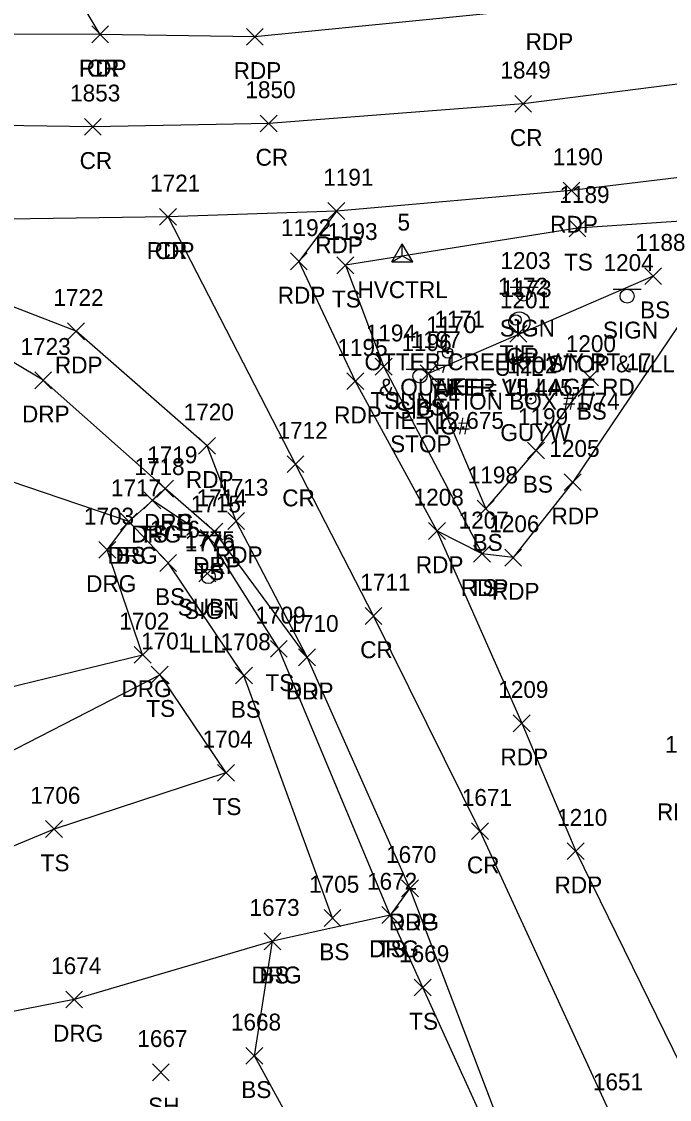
# Model space of a CAD drawing. Extents: x 1443590 to 1445966, y 578314 to 580556.
# Drawn here: x 1445125.4 to 1445202.2, y 578975.6 to 579103.3 of the extents above; entities that cross this region are included whole.
import ezdxf

# ---------------------------------------------------------------- set-up
doc = ezdxf.new("R2010")
doc.units = 0
for name, color, linetype in [('C_A', 7, 'Continuous'), ('C_C', 7, 'Continuous'), ('C_I', 7, 'Continuous'), ('CBP', 7, 'Continuous'), ('CPSM', 7, 'Continuous'), ('L_A', 7, 'Continuous'), ('L_I', 7, 'Continuous'), ('L_TIC', 7, 'Continuous'), ('LELB', 7, 'Continuous'), ('P_A', 7, 'Continuous'), ('P_I', 7, 'Continuous'), ('P_TIC', 7, 'Continuous'), ('PET', 7, 'Continuous'), ('PRC', 7, 'Continuous'), ('R_A', 7, 'Continuous'), ('R_I', 7, 'Continuous'), ('R_TIC', 7, 'Continuous'), ('RDG', 7, 'Continuous'), ('RDP', 7, 'Continuous'), ('RGP', 7, 'Continuous'), ('S_A', 7, 'Continuous'), ('S_C', 7, 'Continuous'), ('S_I', 7, 'Continuous'), ('SSGN', 7, 'Continuous'), ('U_A', 7, 'Continuous'), ('U_C', 7, 'Continuous'), ('U_I', 7, 'Continuous'), ('U_TIC', 7, 'Continuous'), ('UDEFAULT', 7, 'Continuous'), ('UEPT', 7, 'Continuous'), ('UPGW', 7, 'Continuous')]:
    doc.layers.add(name, color=color, linetype=linetype)

msp = doc.modelspace()

# ---------------------------------------------------------------- linework, layer by layer
at = {"layer": 'CBP'}
for centre, radius in [((1445183.97, 579067.97), 0.625), ((1445183.97, 579067.97), 0.0833), ((1445175.88, 579064.07), 0.625), ((1445175.88, 579064.07), 0.0833)]:
    msp.add_circle(centre, radius, dxfattribs=at)
at = {"layer": 'CPSM'}
for p, q in [((1445169.26, 579074.84), (1445170.51, 579077)), ((1445171.76, 579074.84), (1445170.51, 579077)), ((1445170.51, 579075.56), (1445170.51, 579077)), ((1445169.26, 579074.84), (1445170.51, 579075.56)), ((1445170.51, 579075.56), (1445170.51, 579075.56)), ((1445170.51, 579075.56), (1445171.76, 579074.84)), ((1445169.26, 579074.84), (1445171.76, 579074.84))]:
    msp.add_line(p, q, dxfattribs=at)
at = {"layer": 'L_TIC'}
for points in [[(1445190.27, 579077.83), (1445192.27, 579079.83)], [(1445192.27, 579077.83), (1445190.27, 579079.83)], [(1445162.76, 579073.45), (1445164.76, 579075.45)], [(1445164.76, 579073.45), (1445162.76, 579075.45)], [(1445199.25, 579072.16), (1445201.25, 579074.16)], [(1445201.25, 579072.16), (1445199.25, 579074.16)], [(1445167.31, 579061.43), (1445169.31, 579063.43)], [(1445169.31, 579061.43), (1445167.31, 579063.43)], [(1445172.62, 579060.64), (1445174.62, 579062.64)], [(1445174.62, 579060.64), (1445172.62, 579062.64)], [(1445191.75, 579060.16), (1445193.75, 579062.16)], [(1445193.75, 579060.16), (1445191.75, 579062.16)], [(1445185.36, 579051.51), (1445187.36, 579053.51)], [(1445187.36, 579051.51), (1445185.36, 579053.51)], [(1445139.88, 579045.6), (1445141.88, 579047.6)], [(1445141.88, 579045.6), (1445139.88, 579047.6)], [(1445179.4, 579044.61), (1445181.4, 579046.61)], [(1445181.4, 579044.61), (1445179.4, 579046.61)], [(1445137.09, 579043.08), (1445139.09, 579045.08)], [(1445139.09, 579043.08), (1445137.09, 579045.08)], [(1445146.56, 579041.16), (1445148.56, 579043.16)], [(1445148.56, 579041.16), (1445146.56, 579043.16)], [(1445178.96, 579039.26), (1445180.96, 579041.26)], [(1445180.96, 579039.26), (1445178.96, 579041.26)], [(1445141.75, 579038.18), (1445143.75, 579040.18)], [(1445143.75, 579038.18), (1445141.75, 579040.18)], [(1445154.88, 579028), (1445156.88, 579030)], [(1445156.88, 579028), (1445154.88, 579030)], [(1445140.75, 579024.94), (1445142.75, 579026.94)], [(1445142.75, 579024.94), (1445140.75, 579026.94)], [(1445150.74, 579024.84), (1445152.74, 579026.84)], [(1445152.74, 579024.84), (1445150.74, 579026.84)], [(1445148.61, 579013.31), (1445150.61, 579015.31)], [(1445150.61, 579013.31), (1445148.61, 579015.31)], [(1445128.23, 579006.65), (1445130.23, 579008.65)], [(1445130.23, 579006.65), (1445128.23, 579008.65)], [(1445168.07, 578996.46), (1445170.07, 578998.46)], [(1445170.07, 578996.46), (1445168.07, 578998.46)], [(1445161.23, 578996.11), (1445163.23, 578998.11)], [(1445163.23, 578996.11), (1445161.23, 578998.11)], [(1445154.13, 578993.36), (1445156.13, 578995.36)], [(1445156.13, 578993.36), (1445154.13, 578995.36)], [(1445171.93, 578987.88), (1445173.93, 578989.88)], [(1445173.93, 578987.88), (1445171.93, 578989.88)], [(1445151.98, 578979.78), (1445153.98, 578981.78)], [(1445153.98, 578979.78), (1445151.98, 578981.78)], [(1445140.89, 578977.83), (1445142.89, 578979.83)], [(1445142.89, 578977.83), (1445140.89, 578979.83)]]:
    msp.add_lwpolyline(points, dxfattribs=at)
at = {"layer": 'LELB'}
for points in [[(1445162.23, 578997.11), (1445151.74, 579025.84), (1445142.75, 579039.18), (1445138.09, 579044.08), (1445116.07, 579051.55), (1445101.92, 579061.67), (1445096.63, 579066.95), (1445066.06, 579065.72), (1445043.59, 579063.21), (1445031.62, 579065.51), (1445012.31, 579070.54), (1445010.25, 579074.37), (1444988.26, 579078.47), (1444956.32, 579080.59), (1444930.53, 579082.81), (1444916.43, 579086.33), (1444911.23, 579088.69), (1444908.49, 579088.65), (1444906.17, 579094.71), (1444893.92, 579096.75), (1444853.12, 579100.69), (1444811.04, 579100.21)], [(1445213.49, 579080.35), (1445191.27, 579078.83), (1445163.76, 579074.45), (1445168.31, 579062.43), (1445179.96, 579040.26)], [(1445200.25, 579073.16), (1445173.62, 579061.64), (1445180.4, 579045.61), (1445186.36, 579052.51), (1445192.75, 579061.16)], [(1445182.47, 578967.95), (1445172.93, 578988.88), (1445169.07, 578997.46), (1445155.88, 579029), (1445147.56, 579042.16), (1445140.88, 579046.6)], [(1445098.85, 579002.94), (1445095.12, 579014.79), (1445092.53, 579021.51), (1445092.27, 579024.59), (1445114.64, 579017.07), (1445121.81, 579015.68), (1445141.75, 579025.94), (1445149.61, 579014.31), (1445129.23, 579007.65), (1445107.45, 578998.59)], [(1445190.79, 578941.35), (1445175.18, 578951.44), (1445164.42, 578959.92), (1445152.98, 578980.78), (1445155.13, 578994.36)]]:
    msp.add_lwpolyline(points, dxfattribs=at)
at = {"layer": 'P_TIC'}
for points in [[(1445133.69, 579100.81), (1445135.69, 579102.81)], [(1445135.69, 579100.81), (1445133.69, 579102.81)], [(1445133.69, 579100.81), (1445135.69, 579102.81)], [(1445135.69, 579100.81), (1445133.69, 579102.81)], [(1445152.03, 579100.52), (1445154.03, 579102.52)], [(1445154.03, 579100.52), (1445152.03, 579102.52)], [(1445183.84, 579092.58), (1445185.84, 579094.58)], [(1445185.84, 579092.58), (1445183.84, 579094.58)], [(1445132.82, 579089.86), (1445134.82, 579091.86)], [(1445134.82, 579089.86), (1445132.82, 579091.86)], [(1445153.68, 579090.25), (1445155.68, 579092.25)], [(1445155.68, 579090.25), (1445153.68, 579092.25)], [(1445189.56, 579082.31), (1445191.56, 579084.31)], [(1445191.56, 579082.31), (1445189.56, 579084.31)], [(1445161.7, 579079.88), (1445163.7, 579081.88)], [(1445163.7, 579079.88), (1445161.7, 579081.88)], [(1445161.7, 579079.88), (1445163.7, 579081.88)], [(1445163.7, 579079.88), (1445161.7, 579081.88)], [(1445141.74, 579079.19), (1445143.74, 579081.19)], [(1445143.74, 579079.19), (1445141.74, 579081.19)], [(1445141.74, 579079.19), (1445143.74, 579081.19)], [(1445143.74, 579079.19), (1445141.74, 579081.19)], [(1445157.25, 579073.91), (1445159.25, 579075.91)], [(1445159.25, 579073.91), (1445157.25, 579075.91)], [(1445130.84, 579065.63), (1445132.84, 579067.63)], [(1445132.84, 579065.63), (1445130.84, 579067.63)], [(1445163.94, 579059.72), (1445165.94, 579061.72)], [(1445165.94, 579059.72), (1445163.94, 579061.72)], [(1445146.37, 579052.06), (1445148.37, 579054.06)], [(1445148.37, 579052.06), (1445146.37, 579054.06)], [(1445156.85, 579049.89), (1445158.85, 579051.89)], [(1445158.85, 579049.89), (1445156.85, 579051.89)], [(1445189.71, 579047.75), (1445191.71, 579049.75)], [(1445191.71, 579047.75), (1445189.71, 579049.75)], [(1445149.81, 579043.14), (1445151.81, 579045.14)], [(1445151.81, 579043.14), (1445149.81, 579045.14)], [(1445173.62, 579041.97), (1445175.62, 579043.97)], [(1445175.62, 579041.97), (1445173.62, 579043.97)], [(1445173.62, 579041.97), (1445175.62, 579043.97)], [(1445175.62, 579041.97), (1445173.62, 579043.97)], [(1445178.96, 579039.26), (1445180.96, 579041.26)], [(1445180.96, 579039.26), (1445178.96, 579041.26)], [(1445182.65, 579038.82), (1445184.65, 579040.82)], [(1445184.65, 579038.82), (1445182.65, 579040.82)], [(1445166.09, 579031.9), (1445168.09, 579033.9)], [(1445168.09, 579031.9), (1445166.09, 579033.9)], [(1445158.22, 579027.01), (1445160.22, 579029.01)], [(1445160.22, 579027.01), (1445158.22, 579029.01)], [(1445183.66, 579019.19), (1445185.66, 579021.19)], [(1445185.66, 579019.19), (1445183.66, 579021.19)], [(1445178.73, 579006.4), (1445180.73, 579008.4)], [(1445180.73, 579006.4), (1445178.73, 579008.4)], [(1445190.07, 579004.03), (1445192.07, 579006.03)], [(1445192.07, 579004.03), (1445190.07, 579006.03)], [(1445170.41, 578999.64), (1445172.41, 579001.64)], [(1445172.41, 578999.64), (1445170.41, 579001.64)]]:
    msp.add_lwpolyline(points, dxfattribs=at)
at = {"layer": 'PET'}
for points in [[(1445501.67, 579168.43), (1445455.4, 579157.53), (1445415.83, 579148.65), (1445383.99, 579140.98), (1445332.83, 579129.97), (1445290.54, 579120.7), (1445257.45, 579113.85), (1445222.94, 579108.87), (1445187.64, 579104.95), (1445153.03, 579101.52), (1445134.69, 579101.81), (1445094.76, 579101.93)], [(1445505.3, 579147.27), (1445460.87, 579137.08), (1445420.41, 579128.61), (1445387.54, 579120.65), (1445337.52, 579109.35), (1445293.82, 579099.75), (1445262.55, 579093.02), (1445250.68, 579090.5), (1445218.05, 579086.64), (1445190.56, 579083.31), (1445162.7, 579080.88), (1445142.74, 579080.19), (1445099.09, 579079.55)], [(1445218.05, 579086.64), (1445213.49, 579080.35), (1445206.62, 579072.29), (1445190.71, 579048.75), (1445183.65, 579039.82), (1445179.96, 579040.26), (1445174.62, 579042.97)], [(1445162.7, 579080.88), (1445158.25, 579074.91), (1445164.94, 579060.72), (1445174.62, 579042.97), (1445184.66, 579020.19), (1445191.07, 579005.03), (1445204.47, 578977.72)], [(1445183.72, 578968.31), (1445171.41, 579000.64), (1445159.22, 579028.01), (1445150.81, 579044.14), (1445147.37, 579053.06), (1445131.84, 579066.63), (1445104.03, 579077.4), (1445099.09, 579079.55)]]:
    msp.add_lwpolyline(points, dxfattribs=at)
at = {"layer": 'PRC'}
for points in [[(1445134.69, 579101.81), (1445120.96, 579124.75), (1445105.7, 579149.31), (1445088.61, 579176.47), (1445062.61, 579215.94), (1445046.37, 579243.3), (1445028.61, 579272.2), (1445009.91, 579303.07), (1444988.59, 579337.21), (1444961.47, 579379.67), (1444937.03, 579417.04), (1444911.02, 579455.05), (1444885.8, 579491.61), (1444860.37, 579528.28), (1444835.41, 579566.04), (1444809.93, 579606.59), (1444790.8, 579639.57), (1444773.48, 579670.26), (1444758.9, 579698.36)], [(1445503.37, 579157.52), (1445457.64, 579146.91), (1445418.46, 579138.08), (1445385.47, 579130.53), (1445335.24, 579119.44), (1445292.05, 579110.36), (1445260.01, 579104.38), (1445221.4, 579098.24), (1445184.84, 579093.58), (1445154.68, 579091.25), (1445133.82, 579090.86), (1445081.89, 579091.59)], [(1445428.76, 578345.92), (1445416.12, 578381.06), (1445402.82, 578417.2), (1445394.53, 578440.03), (1445382.79, 578472.56), (1445367.55, 578515.78), (1445354.3, 578552.77), (1445340.07, 578591.68), (1445332.93, 578610.75), (1445320.05, 578646.79), (1445306.48, 578683.94), (1445294.78, 578715.83), (1445285.68, 578740.23), (1445278.69, 578759.19), (1445266.72, 578790.29), (1445259.42, 578810.95), (1445240.14, 578861.33), (1445228.56, 578891.21), (1445209.9, 578937.12), (1445195.27, 578973.7), (1445179.73, 579007.4), (1445167.09, 579032.9), (1445157.85, 579050.89), (1445142.74, 579080.19)]]:
    msp.add_lwpolyline(points, dxfattribs=at)
at = {"layer": 'R_TIC'}
for points in [[(1445126.94, 579059.83), (1445128.94, 579061.83)], [(1445128.94, 579059.83), (1445126.94, 579061.83)], [(1445141.4, 579046.99), (1445143.4, 579048.99)], [(1445143.4, 579046.99), (1445141.4, 579048.99)], [(1445141.4, 579046.99), (1445143.4, 579048.99)], [(1445143.4, 579046.99), (1445141.4, 579048.99)], [(1445139.88, 579045.6), (1445141.88, 579047.6)], [(1445141.88, 579045.6), (1445139.88, 579047.6)], [(1445137.09, 579043.08), (1445139.09, 579045.08)], [(1445139.09, 579043.08), (1445137.09, 579045.08)], [(1445147.24, 579041.89), (1445149.24, 579043.89)], [(1445149.24, 579041.89), (1445147.24, 579043.89)], [(1445134.54, 579039.73), (1445136.54, 579041.73)], [(1445136.54, 579039.73), (1445134.54, 579041.73)], [(1445138.73, 579027.29), (1445140.73, 579029.29)], [(1445140.73, 579027.29), (1445138.73, 579029.29)], [(1445158.22, 579027.01), (1445160.22, 579029.01)], [(1445160.22, 579027.01), (1445158.22, 579029.01)], [(1445170.41, 578999.64), (1445172.41, 579001.64)], [(1445172.41, 578999.64), (1445170.41, 579001.64)], [(1445168.07, 578996.46), (1445170.07, 578998.46)], [(1445170.07, 578996.46), (1445168.07, 578998.46)], [(1445154.13, 578993.36), (1445156.13, 578995.36)], [(1445156.13, 578993.36), (1445154.13, 578995.36)], [(1445130.62, 578986.46), (1445132.62, 578988.46)], [(1445132.62, 578986.46), (1445130.62, 578988.46)]]:
    msp.add_lwpolyline(points, dxfattribs=at)
at = {"layer": 'RDG'}
msp.add_lwpolyline([(1445171.41, 579000.64), (1445169.07, 578997.46), (1445155.13, 578994.36), (1445131.62, 578987.46), (1445107.99, 578982.85), (1445100.96, 578995.31), (1445097.63, 579001.55), (1445090.1, 579013.19), (1445087.39, 579022.78), (1445089.24, 579027.02), (1445107.09, 579036.55), (1445117, 579022.75), (1445139.73, 579028.29), (1445135.54, 579040.73), (1445138.09, 579044.08), (1445140.88, 579046.6), (1445142.4, 579047.99)], dxfattribs=at)
at = {"layer": 'RDP'}
msp.add_lwpolyline([(1445159.22, 579028.01), (1445148.24, 579042.89), (1445142.4, 579047.99), (1445127.94, 579060.83), (1445111.1, 579070.88), (1445104.71, 579074.23), (1445104.03, 579077.4)], dxfattribs=at)
at = {"layer": 'RGP'}
msp.add_line((1445184.39, 579067.68), (1445184.39, 579067.68), dxfattribs=at)
for radius in [1.25, 0.0833]:
    msp.add_circle((1445184.39, 579067.68), radius, dxfattribs=at)
at = {"layer": 'SSGN'}
for p, q in [((1445183.29, 579071.87), (1445186.62, 579071.87)), ((1445195.51, 579071.62), (1445198.84, 579071.62)), ((1445184.93, 579071.03), (1445184.93, 579071.03)), ((1445197.15, 579070.79), (1445197.15, 579070.79)), ((1445170.96, 579062.14), (1445174.3, 579062.14)), ((1445172.61, 579061.31), (1445172.61, 579061.31)), ((1445145.86, 579038.4), (1445149.2, 579038.4)), ((1445147.51, 579037.57), (1445147.51, 579037.57))]:
    msp.add_line(p, q, dxfattribs=at)
for centre in [(1445184.93, 579071.03), (1445197.15, 579070.79), (1445172.61, 579061.31), (1445147.51, 579037.57)]:
    msp.add_circle(centre, 0.833, dxfattribs=at)
at = {"layer": 'U_TIC'}
for points in [[(1445146.39, 579036.93), (1445148.39, 579038.93)], [(1445148.39, 579036.93), (1445146.39, 579038.93)]]:
    msp.add_lwpolyline(points, dxfattribs=at)
at = {"layer": 'UDEFAULT'}
for points in [[(1445183.27, 579065.35), (1445185.27, 579067.35)], [(1445185.27, 579065.35), (1445183.27, 579067.35)]]:
    msp.add_lwpolyline(points, dxfattribs=at)
at = {"layer": 'UEPT'}
for p, q in [((1445175.71, 579065.07), (1445175.55, 579064.24)), ((1445174.71, 579062.57), (1445174.71, 579064.24)), ((1445174.71, 579064.24), (1445176.38, 579064.24)), ((1445176.38, 579064.24), (1445176.38, 579062.57)), ((1445176.38, 579062.57), (1445174.71, 579062.57)), ((1445175.3, 579061.74), (1445175.55, 579062.57)), ((1445175.55, 579063.41), (1445175.55, 579063.41))]:
    msp.add_line(p, q, dxfattribs=at)
at = {"layer": 'UPGW'}
for radius in [0.625, 0.0833]:
    msp.add_circle((1445185.73, 579058.63), radius, dxfattribs=at)

# ---------------------------------------------------------------- texts
at = {"layer": 'C_A'}
for s, p in [('HVCTRL', (1445165.2, 579070.56)), ('TIE', (1445182.05, 579062.97)), ('TIE', (1445173.96, 579059.07))]:
    msp.add_text(s, height=2, dxfattribs=at).set_placement(p)
at = {"layer": 'C_C'}
for s, p in [('TIE= 15.445', (1445176.05, 579058.97)), ('TIE= 12.675', (1445167.91, 579055.07))]:
    msp.add_text(s, height=2, dxfattribs=at).set_placement(p)
at = {"layer": 'C_I'}
for s, p in [('5', (1445169.94, 579078.56)), ('1172', (1445181.84, 579070.97)), ('1171', (1445174.32, 579067.07))]:
    msp.add_text(s, height=2, dxfattribs=at).set_placement(p)
at = {"layer": 'L_A'}
for s, p in [('TS', (1445189.68, 579073.83)), ('TS', (1445162.17, 579069.45)), ('BS', (1445198.69, 579068.16)), ('TS', (1445166.72, 579057.43)), ('BS', (1445172.06, 579056.64)), ('BS', (1445191.19, 579056.16)), ('BS', (1445184.8, 579047.51)), ('TS', (1445139.29, 579041.6)), ('BS', (1445178.84, 579040.61)), ('BS', (1445136.53, 579039.08)), ('TS', (1445145.96, 579037.16)), ('TS', (1445178.37, 579035.26)), ('BS', (1445141.2, 579034.18)), ('TS', (1445154.29, 579024)), ('TS', (1445140.16, 579020.94)), ('BS', (1445150.18, 579020.84)), ('TS', (1445148.02, 579009.31)), ('TS', (1445127.64, 579002.65)), ('BS', (1445160.67, 578992.11)), ('TS', (1445167.48, 578992.46)), ('BS', (1445153.57, 578989.36)), ('TS', (1445171.33, 578983.88)), ('BS', (1445151.42, 578975.78)), ('SH', (1445140.38, 578973.83))]:
    msp.add_text(s, height=2, dxfattribs=at).set_placement(p)
at = {"layer": 'L_I'}
for s, p in [('1189', (1445189.13, 579081.83)), ('1193', (1445161.63, 579077.45)), ('1188', (1445198.13, 579076.16)), ('1194', (1445166.18, 579065.43)), ('1197', (1445171.49, 579064.64)), ('1200', (1445189.89, 579064.16)), ('1199', (1445184.22, 579055.51)), ('1718', (1445138.75, 579049.6)), ('1198', (1445178.27, 579048.61)), ('1717', (1445135.97, 579047.08)), ('1715', (1445145.43, 579045.16)), ('1207', (1445177.18, 579043.26)), ('1716', (1445140.57, 579042.18)), ('1709', (1445153.1, 579032)), ('1701', (1445139.55, 579028.94)), ('1708', (1445148.96, 579028.84)), ('1704', (1445146.83, 579017.31)), ('1706', (1445126.4, 579010.65)), ('1672', (1445166.33, 579000.46)), ('1705', (1445159.46, 579000.11)), ('1673', (1445152.39, 578997.36)), ('1669', (1445170.13, 578991.88)), ('1668', (1445150.19, 578983.78)), ('1667', (1445139.1, 578981.83))]:
    msp.add_text(s, height=2, dxfattribs=at).set_placement(p)
at = {"layer": 'P_A'}
for s, p in [('RDP', (1445185.13, 579099.95)), ('RDP', (1445185.13, 579099.95)), ('RDP', (1445132.18, 579096.81)), ('CR', (1445133.12, 579096.81)), ('RDP', (1445150.52, 579096.52)), ('CR', (1445183.27, 579088.58)), ('CR', (1445132.26, 579085.86)), ('CR', (1445153.12, 579086.25)), ('RDP', (1445188.04, 579078.31)), ('RDP', (1445160.19, 579075.88)), ('RDP', (1445160.19, 579075.88)), ('RDP', (1445140.23, 579075.19)), ('CR', (1445141.17, 579075.19)), ('RDP', (1445155.74, 579069.91)), ('RDP', (1445129.33, 579061.63)), ('RDP', (1445162.43, 579055.72)), ('RDP', (1445144.86, 579048.06)), ('CR', (1445156.28, 579045.89)), ('RDP', (1445188.2, 579043.75)), ('RDP', (1445148.3, 579039.14)), ('RDP', (1445172.11, 579037.97)), ('RDP', (1445172.11, 579037.97)), ('RDP', (1445177.44, 579035.26)), ('RDP', (1445181.13, 579034.82)), ('CR', (1445165.52, 579027.9)), ('RDP', (1445156.71, 579023.01)), ('RDP', (1445182.15, 579015.19)), ('RDP', (1445200.7, 579008.69)), ('CR', (1445178.17, 579002.4)), ('RDP', (1445188.56, 579000.03)), ('RDP', (1445168.9, 578995.64))]:
    msp.add_text(s, height=2, dxfattribs=at).set_placement(p)
at = {"layer": 'P_I'}
for s, p in [('1849', (1445182.14, 579096.58)), ('1853', (1445131.13, 579093.86)), ('1850', (1445151.91, 579094.25)), ('1190', (1445188.34, 579086.31)), ('1191', (1445161.14, 579083.88)), ('1191', (1445161.14, 579083.88)), ('1721', (1445140.61, 579083.19)), ('1721', (1445140.61, 579083.19)), ('1192', (1445156.13, 579077.91)), ('1722', (1445129.15, 579069.63)), ('1195', (1445162.81, 579063.72)), ('1720', (1445144.59, 579056.06)), ('1712', (1445155.72, 579053.89)), ('1205', (1445187.94, 579051.75)), ('1713', (1445148.69, 579047.14)), ('1208', (1445171.85, 579045.97)), ('1208', (1445171.85, 579045.97)), ('1207', (1445177.18, 579043.26)), ('1206', (1445180.82, 579042.82)), ('1711', (1445165.53, 579035.9)), ('1710', (1445157.01, 579031.01)), ('1209', (1445181.88, 579023.19)), ('1211', (1445201.66, 579016.69)), ('1671', (1445177.56, 579010.4)), ('1210', (1445188.86, 579008.03)), ('1670', (1445168.59, 579003.64)), ('1651', (1445193.1, 578976.7))]:
    msp.add_text(s, height=2, dxfattribs=at).set_placement(p)
at = {"layer": 'R_A'}
for s, p in [('GP', (1445182.82, 579062.68)), ('DRP', (1445125.43, 579055.83)), ('DRG', (1445139.89, 579042.99)), ('DRP', (1445139.89, 579042.99)), ('DRG', (1445138.37, 579041.6)), ('DRG', (1445135.58, 579039.08)), ('DRP', (1445145.73, 579037.89)), ('DRG', (1445133.03, 579035.73)), ('DRG', (1445137.22, 579023.29)), ('DRP', (1445156.71, 579023.01)), ('DRG', (1445168.9, 578995.64)), ('DRG', (1445166.56, 578992.46)), ('DRG', (1445152.62, 578989.36)), ('DRG', (1445129.11, 578982.46))]:
    msp.add_text(s, height=2, dxfattribs=at).set_placement(p)
at = {"layer": 'R_I'}
for s, p in [('1173', (1445182.26, 579070.68)), ('1723', (1445125.25, 579063.83)), ('1719', (1445140.27, 579050.99)), ('1719', (1445140.27, 579050.99)), ('1718', (1445138.75, 579049.6)), ('1717', (1445135.97, 579047.08)), ('1714', (1445146.12, 579045.89)), ('1703', (1445132.77, 579043.73)), ('1702', (1445136.96, 579031.29)), ('1710', (1445157.01, 579031.01)), ('1670', (1445168.59, 579003.64)), ('1672', (1445166.33, 579000.46)), ('1673', (1445152.39, 578997.36)), ('1674', (1445128.88, 578990.46))]:
    msp.add_text(s, height=2, dxfattribs=at).set_placement(p)
at = {"layer": 'S_A'}
for p in [(1445182.07, 579066.01), (1445194.29, 579065.77), (1445169.75, 579056.29), (1445144.65, 579032.55)]:
    msp.add_text('SIGN', height=2, dxfattribs=at).set_placement(p)
at = {"layer": 'S_C'}
for s, p in [('OTTER CREEK HWY RT 17', (1445166.03, 579062.01)), ('STOP & LLL', (1445187.81, 579061.77)), ('& QUAKER VILLAGE RD', (1445167.74, 579059.01)), ('STOP', (1445169.07, 579052.29)), ('LLL', (1445145.13, 579028.55))]:
    msp.add_text(s, height=2, dxfattribs=at).set_placement(p)
at = {"layer": 'S_I'}
for s, p in [('1203', (1445182.14, 579074.01)), ('1204', (1445194.36, 579073.77)), ('1196', (1445170.41, 579064.29)), ('1776', (1445144.74, 579040.55))]:
    msp.add_text(s, height=2, dxfattribs=at).set_placement(p)
at = {"layer": 'U_A'}
for s, p in [('UTIL', (1445181.44, 579061.35)), ('EL', (1445174.08, 579058.41)), ('GUYW', (1445182.13, 579053.63)), ('SUBT', (1445143.89, 579032.93))]:
    msp.add_text(s, height=2, dxfattribs=at).set_placement(p)
at = {"layer": 'U_C'}
for s, p in [('JUNCTION BOX #1/74', (1445168.92, 579057.35)), ('NO#', (1445173.06, 579054.41))]:
    msp.add_text(s, height=2, dxfattribs=at).set_placement(p)
at = {"layer": 'U_I'}
for s, p in [('1201', (1445182.07, 579069.35)), ('1170', (1445173.34, 579066.41)), ('1202', (1445182.96, 579061.63)), ('1775', (1445144.7, 579040.93))]:
    msp.add_text(s, height=2, dxfattribs=at).set_placement(p)

doc.saveas('drawing.dxf')
